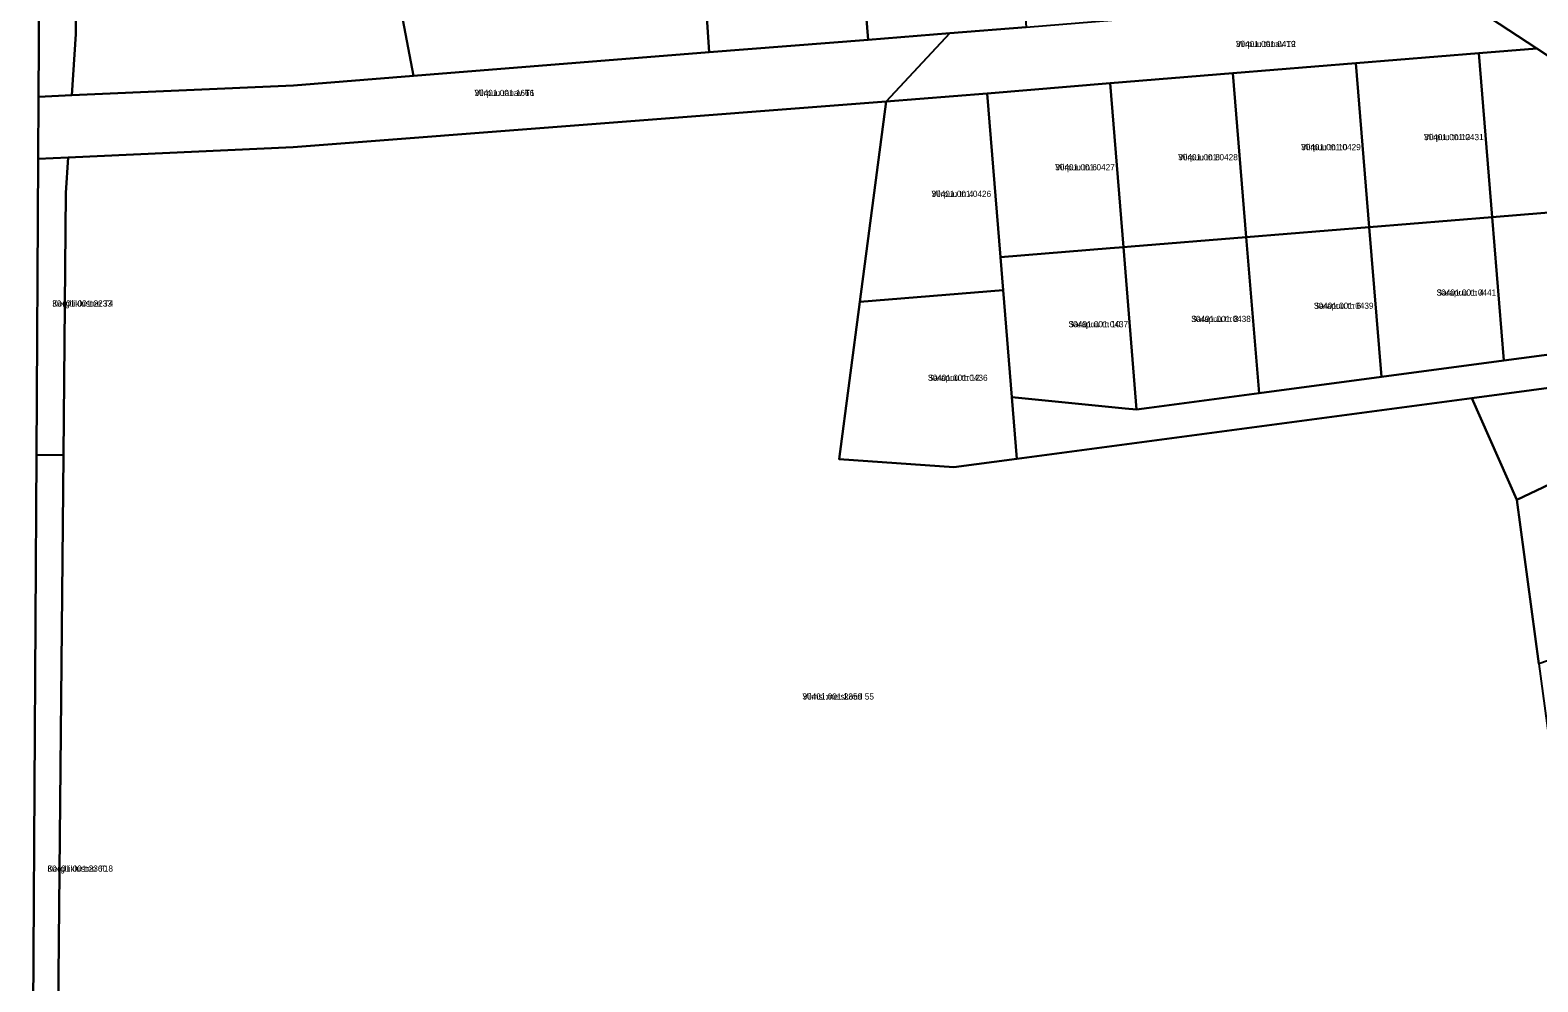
# Model space of a CAD drawing. Extents: x 542681 to 554572, y 6566489 to 6580482.
# Drawn here: x 544055.6 to 544422.3, y 6578789.4 to 6579020.8 of the extents above; entities that cross this region are included whole.
import ezdxf

# ---------------------------------------------------------------- set-up
doc = ezdxf.new("R2010")
doc.units = 0
for name, color, linetype in [('L_AADRESS', 7, 'Continuous'), ('PIIR', 7, 'Continuous'), ('TUNNUS', 7, 'Continuous')]:
    doc.layers.add(name, color=color, linetype=linetype)

msp = doc.modelspace()

# ---------------------------------------------------------------- linework, layer by layer
at = {"layer": 'PIIR'}
for points in [[(543901.62, 6579945.16), (543962.58, 6579800.57), (543977.04, 6579757), (543995.75, 6579698.2), (544028.37, 6579595.71), (544037.12, 6579558.18), (544044.41, 6579521.69), (544051.46, 6579476.56), (544055.51, 6579438.45), (544058.68, 6579397.02), (544059.06, 6579385), (544058.72, 6579358.82), (544058.35, 6579205.94), (544058.44, 6579198.68), (544057.98, 6579055.68), (544057.67, 6579004.59), (544057.58, 6578989.54), (544057.15, 6578917.53), (544055.93, 6578714.9)], [(544061.82, 6578714.84), (544063.75, 6578917.49), (544064.29, 6578981.25), (544064.9, 6578989.87), (544119.63, 6578992.36), (544263.86, 6579003.43), (544257.44, 6578954.75), (544252.39, 6578916.45), (544280.26, 6578914.55), (544295.62, 6578916.6), (544406.27, 6578931.34), (544417.19, 6578906.62), (544422.58, 6578866.72), (544428.42, 6578823.44), (544431.77, 6578798.63), (544433.12, 6578787.58)], [(544443.14, 6578936.25), (544406.27, 6578931.34), (544295.62, 6578916.6), (544294.4, 6578931.57), (544321.98, 6578928.82), (544324.75, 6578928.55), (544327.76, 6578928.95), (544354.52, 6578932.52), (544384.3, 6578936.48), (544414.07, 6578940.45), (544442.3, 6578944.21)]]:
    msp.add_lwpolyline(points, dxfattribs=at)
for points in [[(544220.79, 6579015.41), (544217.27, 6579067.55), (544220.04, 6579067.78), (544255.23, 6579070.4), (544259.49, 6579018.47)], [(544259.49, 6579018.47), (544255.23, 6579070.4), (544271.32, 6579071.6), (544293.69, 6579073.25), (544297.9, 6579021.54), (544279.33, 6579020.05)], [(544148.89, 6579009.66), (544138.96, 6579061.71), (544179.52, 6579064.71), (544217.27, 6579067.55), (544220.79, 6579015.41)], [(544066.78, 6579019.86), (544066.92, 6579056.34), (544138.96, 6579061.71), (544148.89, 6579009.66), (544119.69, 6579007.35), (544065.77, 6579004.95)], [(544057.98, 6579055.68), (544066.92, 6579056.34), (544066.78, 6579019.86), (544065.77, 6579004.95), (544057.67, 6579004.59)], [(544401.41, 6579029.94), (544476.16, 6579035.96), (544452.53, 6579018.86), (544436.03, 6579007.14), (544422.07, 6579016.35)], [(544279.33, 6579020.05), (544297.9, 6579021.54), (544335.59, 6579024.6), (544367.47, 6579027.21), (544401.41, 6579029.94), (544422.07, 6579016.35), (544407.97, 6579015.2), (544378.07, 6579012.76), (544348.17, 6579010.32), (544318.27, 6579007.88), (544288.36, 6579005.43), (544263.86, 6579003.43)], [(544263.86, 6579003.43), (544119.63, 6578992.36), (544064.9, 6578989.87), (544057.58, 6578989.54), (544057.67, 6579004.59), (544065.77, 6579004.95), (544119.69, 6579007.35), (544148.89, 6579009.66), (544220.79, 6579015.41), (544259.49, 6579018.47), (544279.33, 6579020.05)], [(544378.07, 6579012.76), (544407.97, 6579015.2), (544411.22, 6578975.34), (544381.32, 6578972.89)], [(544407.97, 6579015.2), (544422.07, 6579016.35), (544436.03, 6579007.14), (544438.88, 6579005.27), (544441.77, 6578977.83), (544411.22, 6578975.34)], [(544348.17, 6579010.32), (544378.07, 6579012.76), (544381.32, 6578972.89), (544351.42, 6578970.45)], [(544288.36, 6579005.43), (544318.27, 6579007.88), (544321.52, 6578968.01), (544318.34, 6578967.75), (544291.62, 6578965.57)], [(544318.27, 6579007.88), (544348.17, 6579010.32), (544351.42, 6578970.45), (544323.39, 6578968.16), (544321.52, 6578968.01)], [(544263.86, 6579003.43), (544288.36, 6579005.43), (544291.62, 6578965.57), (544292.27, 6578957.59), (544257.44, 6578954.75)], [(544057.58, 6578989.54), (544064.9, 6578989.87), (544064.29, 6578981.25), (544063.75, 6578917.49), (544057.15, 6578917.53)], [(544381.32, 6578972.89), (544411.22, 6578975.34), (544414.07, 6578940.45), (544384.3, 6578936.48)], [(544411.22, 6578975.34), (544441.77, 6578977.83), (544444.96, 6578947.59), (544442.3, 6578944.21), (544414.07, 6578940.45)], [(544351.42, 6578970.45), (544381.32, 6578972.89), (544384.3, 6578936.48), (544354.52, 6578932.52)], [(544291.62, 6578965.57), (544318.34, 6578967.75), (544321.52, 6578968.01), (544324.75, 6578928.55), (544321.98, 6578928.82), (544294.4, 6578931.57), (544292.27, 6578957.59)], [(544321.52, 6578968.01), (544323.39, 6578968.16), (544351.42, 6578970.45), (544354.52, 6578932.52), (544327.76, 6578928.95), (544324.75, 6578928.55)], [(544257.44, 6578954.75), (544292.27, 6578957.59), (544294.4, 6578931.57), (544295.62, 6578916.6), (544280.26, 6578914.55), (544252.39, 6578916.45)], [(544406.27, 6578931.34), (544443.14, 6578936.25), (544446.42, 6578933.67), (544447.75, 6578921.08), (544417.19, 6578906.62)], [(544417.19, 6578906.62), (544447.75, 6578921.08), (544452.4, 6578877.02), (544422.58, 6578866.72)], [(544055.93, 6578714.9), (544057.15, 6578917.53), (544063.75, 6578917.49), (544061.82, 6578714.84)]]:
    msp.add_lwpolyline(points, close=True, dxfattribs=at)

# ---------------------------------------------------------------- texts
at = {"layer": 'L_AADRESS'}
for s, p in [('Viirpuu tänav T2', (544348.88, 6579016.69)), ('Viirpuu tänav T1', (544163.71, 6579004.79)), ('Viirpuu tn 10', (544364.75, 6578991.61)), ('Viirpuu tn 12', (544394.64, 6578994.05)), ('Viirpuu tn 8', (544334.85, 6578989.16)), ('Viirpuu tn 6', (544304.94, 6578986.72)), ('Viirpuu tn 4', (544274.86, 6578980.25)), ('Sarapuu tn 4', (544397.7, 6578956.25)), ('Kergliiklustee T4', (544061.02, 6578953.6)), ('Sarapuu tn 6', (544367.86, 6578953.04)), ('Sarapuu tn 10', (544308.18, 6578948.56)), ('Sarapuu tn 8', (544338.02, 6578949.84)), ('Sarapuu tn 12', (544274, 6578935.54)), ('Viimsi metskond 55', (544243.47, 6578858.03)), ('Kergliiklustee T18', (544059.84, 6578816.19))]:
    msp.add_text(s, height=1.5, dxfattribs=at).set_placement(p)
at = {"layer": 'TUNNUS'}
for s, p in [('30401:001:0419', (544348.88, 6579016.69)), ('30401:001:1666', (544163.71, 6579004.79)), ('30401:001:0429', (544364.75, 6578991.61)), ('30401:001:0431', (544394.64, 6578994.05)), ('30401:001:0428', (544334.85, 6578989.16)), ('30401:001:0427', (544304.94, 6578986.72)), ('30401:001:0426', (544274.86, 6578980.25)), ('30401:001:0441', (544397.7, 6578956.25)), ('30401:001:2233', (544061.02, 6578953.6)), ('30401:001:0439', (544367.86, 6578953.04)), ('30401:001:0437', (544308.18, 6578948.56)), ('30401:001:0438', (544338.02, 6578949.84)), ('30401:001:0436', (544274, 6578935.54)), ('30401:001:2359', (544243.47, 6578858.03)), ('30401:001:2360', (544059.84, 6578816.19))]:
    msp.add_text(s, height=1.5, dxfattribs=at).set_placement(p)

doc.saveas('drawing.dxf')
